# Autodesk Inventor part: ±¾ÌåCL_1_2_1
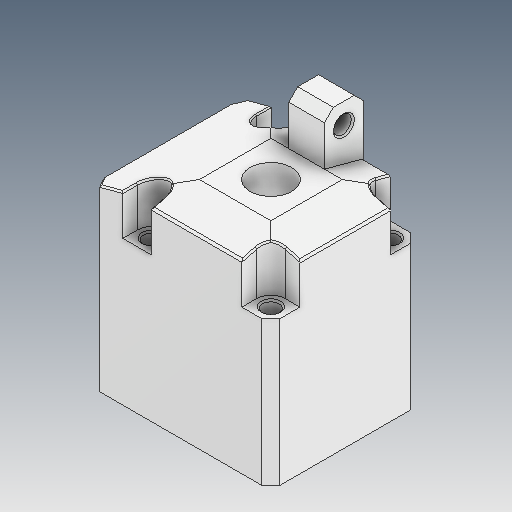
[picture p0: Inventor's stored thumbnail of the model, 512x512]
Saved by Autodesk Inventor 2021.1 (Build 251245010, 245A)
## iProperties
Created: 2021-05
Part Number: ±¾ÌåCL_1_2_1
Material: Ogólny
Document SubType Name: Modeling
Designer: user
Density: 1 g/cm^3
Appearance: Domyślna
Author: user
Revision Number: ÈÎºÎ
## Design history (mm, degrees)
feature "ÊäÈë1"
feature "ÊäÈë2"
node "Bryła1"
node "Bryła2"
